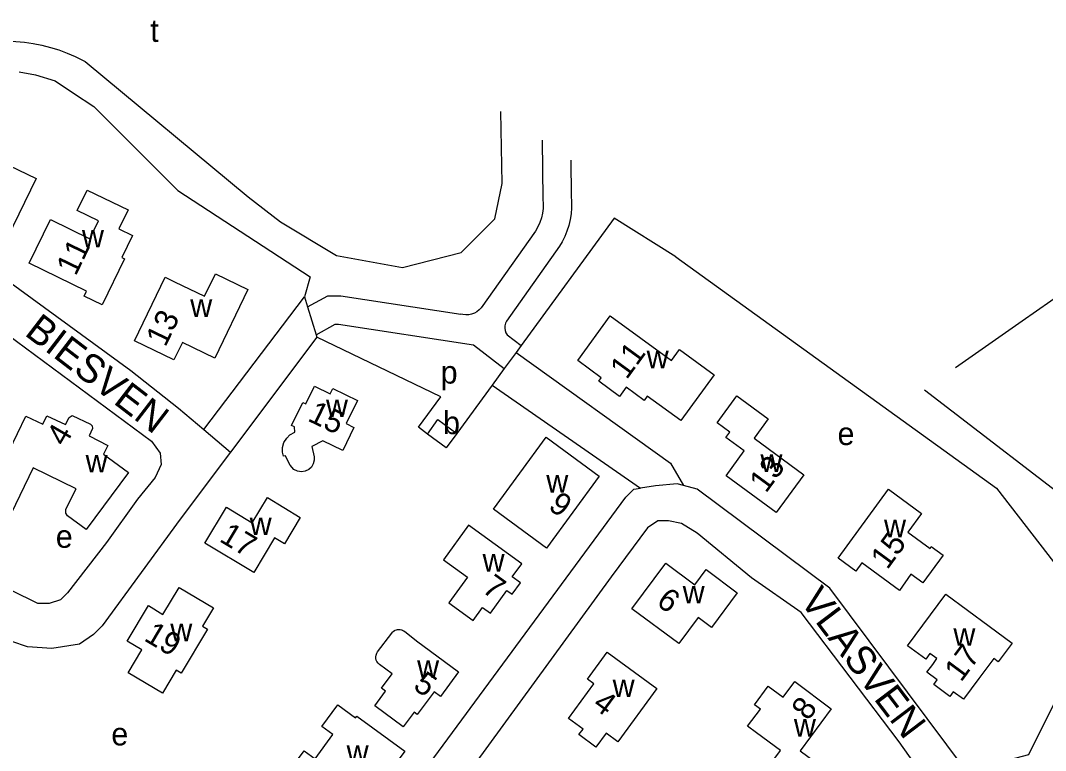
# Model space of a CAD drawing. Extents: x 162667 to 164645, y 379003 to 382150.
# Drawn here: x 163785.6 to 163965.8, y 381498.4 to 381626.7 of the extents above; entities that cross this region are included whole.
import ezdxf

# ---------------------------------------------------------------- set-up
doc = ezdxf.new("R2010")
doc.units = 0
for name, color, linetype in [('BLT_Basislijn', 7, 'Continuous'), ('BLT_Bebouwing', 7, 'Continuous'), ('BLT_Centroide', 7, 'Continuous'), ('BLT_Huisnummer', 7, 'Continuous'), ('BLT_Straatnaam', 7, 'Continuous')]:
    doc.layers.add(name, color=color, linetype=linetype)

msp = doc.modelspace()

# ---------------------------------------------------------------- linework, layer by layer
at = {"layer": 'BLT_Basislijn'}
for p, q in [((163785.42, 381617.69), (163788.3, 381617.15)), ((163788.3, 381617.15), (163791.72, 381616.07)), ((163791.72, 381616.07), (163794.96, 381613.91)), ((163794.96, 381613.91), (163798.56, 381611.57)), ((163798.56, 381611.57), (163813.32, 381596.8)), ((163877.35, 381605.64), (163877.46, 381595.31)), ((163882.35, 381602.16), (163882.43, 381595.86)), ((163813.32, 381596.8), (163836.54, 381581.67)), ((163876.16, 381589.7), (163866.62, 381576.21)), ((163880.38, 381587.02), (163871.08, 381573.87)), ((163836.54, 381581.67), (163835.58, 381578.14)), ((163817.87, 381554.81), (163835.58, 381578.14)), ((163835.58, 381578.14), (163836.11, 381576.38)), ((163836.11, 381576.38), (163837.59, 381571.49)), ((163961.63, 381573.91), (163961.72, 381573.86)), ((163837.59, 381571.49), (163837.73, 381571.04)), ((163871.2, 381571.44), (163873.62, 381569.57)), ((163837.73, 381571.04), (163822.54, 381550.84)), ((163873.62, 381569.57), (163872.75, 381568.38)), ((163872.75, 381568.38), (163870.67, 381565.54)), ((163870.67, 381565.54), (163868.55, 381562.65)), ((163868.55, 381562.65), (163894.62, 381544.54)), ((163817.87, 381554.81), (163822.54, 381550.84))]:
    msp.add_line(p, q, dxfattribs=at)
for points in [[(163771.22, 381620.77), (163772.66, 381621.33), (163774.13, 381621.81), (163775.62, 381622.22), (163777.13, 381622.55), (163778.66, 381622.81), (163780.19, 381622.98), (163781.74, 381623.07), (163783.28, 381623.09), (163784.83, 381623.02), (163786.36, 381622.88), (163787.89, 381622.65), (163789.41, 381622.35), (163790.91, 381621.97), (163792.38, 381621.51), (163793.83, 381620.97), (163795.25, 381620.36), (163796.64, 381619.68), (163797.03, 381619.47)], [(163797.03, 381619.47), (163825.68, 381595.72), (163831.36, 381591.33), (163841.17, 381585.39), (163852.78, 381583.32), (163863.11, 381585.91), (163869.04, 381591.84), (163870.33, 381598.04), (163870.08, 381610.7)], [(164012.05, 381608.99), (163961.72, 381573.86)], [(163877.46, 381595.31), (163877.51, 381594.48), (163877.49, 381593.65), (163877.38, 381592.82), (163877.19, 381592.01), (163876.93, 381591.22), (163876.59, 381590.46), (163876.16, 381589.7)], [(163882.43, 381595.86), (163882.51, 381594.82), (163882.5, 381593.78), (163882.42, 381592.74), (163882.25, 381591.7), (163882.01, 381590.68), (163881.69, 381589.69), (163881.3, 381588.72), (163880.83, 381587.79), (163880.38, 381587.02)], [(163900.81, 381585.17), (163889.99, 381591.98), (163873.62, 381569.57)], [(163900.81, 381585.17), (163957.18, 381544.51), (163974.81, 381521.76)], [(163759.24, 381577.31), (163760.66, 381577.98), (163778.65, 381582.25), (163781.09, 381581.79), (163783.38, 381581.03), (163805.02, 381565.17), (163813.4, 381558.61), (163817.87, 381554.81)], [(163836.11, 381576.38), (163839.69, 381578.33), (163841.94, 381578.33), (163863.05, 381575.11)], [(163866.62, 381576.21), (163866.27, 381575.84), (163865.86, 381575.52), (163865.42, 381575.27), (163864.93, 381575.09), (163864.43, 381574.99), (163863.92, 381574.96), (163863.41, 381575.02), (163863.05, 381575.11)], [(163780.17, 381573.86), (163808.68, 381552.81), (163810.2, 381550.68), (163810.35, 381548.69), (163809.29, 381546.41), (163806.24, 381542.59), (163800.75, 381534.97), (163793.89, 381526.12), (163792.67, 381524.9), (163790.69, 381524.29), (163788.71, 381524.29), (163756.7, 381540), (163755.33, 381541.22), (163754.57, 381543.51), (163755.02, 381547.78), (163759.29, 381567.3), (163760.51, 381569.13), (163762.19, 381570.5), (163778.04, 381574.62), (163780.17, 381573.86)], [(163837.59, 381571.49), (163840.97, 381573.33), (163841.56, 381573.33), (163865.25, 381569.72), (163870.67, 381565.54)], [(163871.08, 381573.87), (163870.9, 381573.49), (163870.8, 381573.07), (163870.78, 381572.65), (163870.84, 381572.23), (163870.97, 381571.83), (163871.2, 381571.44)], [(163961.72, 381573.86), (163949.95, 381565.64)], [(163857.16, 381554.04), (163855.62, 381555.27), (163859.51, 381560.58), (163837.73, 381571.04)], [(163872.75, 381568.38), (163899.9, 381548.92), (163902.16, 381544.97)], [(163868.55, 381562.65), (163862.31, 381554.12)], [(163944.52, 381561.8), (163974.11, 381539.07), (163979.67, 381542.78)], [(163822.54, 381550.84), (163813.71, 381539.08), (163799.99, 381520.32), (163798.46, 381518.8), (163796.02, 381517.12), (163791.15, 381516.36), (163786.88, 381516.66), (163784.14, 381517.58), (163765.54, 381526.73), (163763.56, 381526.12), (163762.49, 381524.75), (163747.85, 381494.11)], [(163849.33, 381433.93), (163866.75, 381458.02), (163868.89, 381460.76), (163869.65, 381462.59), (163869.34, 381465.03), (163868.27, 381466.56), (163854.56, 381476.78), (163852.88, 381479.22), (163851.81, 381482.27), (163851.66, 381485.93), (163852.73, 381489.59), (163892.05, 381542.97), (163893.43, 381544.35), (163894.62, 381544.54)], [(163902.16, 381544.97), (163901.05, 381545.26), (163897.24, 381544.96), (163894.62, 381544.54)], [(163951.94, 381494.82), (163927.87, 381526.96), (163904.55, 381544.35), (163902.16, 381544.97)], [(163914.15, 381528.79), (163904.55, 381536.64), (163901.81, 381538.32), (163899.52, 381538.78), (163897.69, 381538.78), (163895.86, 381537.56), (163889.46, 381528.94), (163859.89, 381488.37), (163858.37, 381485.32), (163858.52, 381482.73), (163859.89, 381480.44), (163908.97, 381444.6), (163911.41, 381443.38), (163913.09, 381443.22), (163915.22, 381443.83), (163917.2, 381445.97), (163947.08, 381486.84), (163947.38, 381488.83), (163946.77, 381490.51), (163940.07, 381499.96), (163922.84, 381522.69), (163914.15, 381528.79)], [(163974.81, 381521.76), (163962.78, 381497.67), (163951.94, 381494.82)]]:
    msp.add_lwpolyline(points, dxfattribs=at)
at = {"layer": 'BLT_Bebouwing'}
msp.add_line((163948.27, 381525.9), (163955.88, 381520.28), dxfattribs=at)
for points in [[(163783.65, 381601.24), (163788.39, 381598.95), (163783.32, 381588.46), (163780.25, 381589.94), (163779.77, 381588.95), (163769.21, 381594.02), (163773.23, 381602.29), (163782.11, 381598.05), (163783.65, 381601.24)], [(163797.37, 381596.91), (163804.56, 381593.43), (163802.94, 381590.1), (163805.36, 381588.92), (163803.48, 381585.03), (163803.93, 381584.82), (163799.99, 381576.72), (163796.82, 381578.26), (163797.26, 381579.15), (163787.19, 381584.04), (163790.91, 381591.7), (163797.84, 381588.33), (163799.37, 381591.47), (163795.61, 381593.29), (163797.37, 381596.91)], [(163819.93, 381582.2), (163825.62, 381579.45), (163819.79, 381567.37), (163814.1, 381570.11), (163812.62, 381567.05), (163805.66, 381570.41), (163811.06, 381581.6), (163812.73, 381580.79), (163818, 381578.24), (163819.93, 381582.2)], [(163889.3, 381574.78), (163900.05, 381566.93), (163901.46, 381568.87), (163907.55, 381564.43), (163901.7, 381556.41), (163895.81, 381560.71), (163895.26, 381559.95), (163892.11, 381562.25), (163890.93, 381560.63), (163887.27, 381563.3), (163887.73, 381563.93), (163883.59, 381566.95), (163889.3, 381574.78)], [(163837.32, 381562.46), (163840.09, 381561.12), (163840.53, 381562.02), (163844.87, 381559.91), (163842.91, 381555.86), (163844.26, 381555.21), (163842.3, 381551.15), (163838.79, 381552.85), (163836.88, 381551.85), (163837.29, 381550.03), (163837.29, 381549.42), (163837.11, 381548.81), (163836.78, 381548.24), (163836.31, 381547.81), (163835.68, 381547.52), (163835.03, 381547.42), (163834.35, 381547.51), (163833.71, 381547.8), (163833.07, 381548.58), (163832.57, 381549.43), (163832.25, 381550.18), (163831.86, 381550.15), (163831.71, 381550.84), (163831.72, 381551.69), (163831.96, 381552.54), (163832.44, 381553.31), (163833.01, 381553.89), (163833.86, 381554.34), (163833.78, 381555.28), (163833.29, 381555.51), (163835.25, 381559.57), (163835.8, 381559.32), (163837.32, 381562.46)], [(163911.57, 381560.74), (163917.07, 381556.7), (163914.58, 381553.3), (163923.31, 381546.88), (163918.45, 381540.26), (163909.65, 381546.72), (163912.84, 381551.06), (163909.62, 381553.43), (163910.31, 381554.36), (163908.08, 381556), (163911.57, 381560.74)], [(163786.59, 381557.17), (163789.55, 381555.75), (163790.28, 381557.26), (163793.57, 381555.7), (163794.2, 381556.93), (163794.73, 381557.31), (163797.93, 381555.79), (163798.24, 381555.48), (163798.31, 381555.02), (163797.74, 381553.71), (163800.97, 381552.04), (163800.25, 381550.51), (163804.65, 381547.28), (163797.18, 381537.24), (163793.89, 381539.69), (163793.59, 381540.15), (163793.59, 381540.84), (163795.42, 381544.42), (163787.87, 381548.09), (163783.18, 381538.39), (163777.73, 381541.03), (163782.79, 381551.49), (163783.64, 381551.08), (163786.59, 381557.17)], [(163857.16, 381554.04), (163859, 381556.58), (163862.31, 381554.12)], [(163862.31, 381554.12), (163860.47, 381551.6), (163857.16, 381554.04)], [(163878.01, 381553.5), (163887.38, 381546.65), (163878.12, 381534), (163868.76, 381540.85), (163878.01, 381553.5)], [(163938.21, 381544.34), (163944.01, 381540.09), (163941.6, 381536.8), (163945.51, 381533.94), (163945.7, 381534.29), (163947.79, 381532.75), (163944.21, 381527.88), (163942.12, 381529.41), (163940.11, 381526.57), (163933.53, 381531.4), (163932.47, 381529.95), (163929.35, 381532.23), (163938.21, 381544.34)], [(163829.04, 381542.87), (163834.82, 381539.4), (163832.04, 381534.76), (163830.3, 381535.81), (163826.63, 381529.7), (163818.05, 381534.86), (163821.84, 381541.18), (163826.39, 381538.45), (163829.04, 381542.87)], [(163873.74, 381531.23), (163864.39, 381538.02), (163859.97, 381531.92), (163864.2, 381528.86), (163860.93, 381524.35), (163865.18, 381521.26), (163866.84, 381523.55), (163868.23, 381522.55), (163871.15, 381526.57), (163872.07, 381525.9), (163873.51, 381527.88), (163872.07, 381528.92), (163873.74, 381531.23)], [(163899.06, 381531.36), (163904.18, 381527.56), (163906.14, 381530.21), (163911.61, 381526.15), (163907.09, 381520.05), (163904.73, 381521.8), (163901.34, 381517.24), (163893.11, 381523.33), (163899.06, 381531.36)], [(163813.51, 381527.08), (163819.55, 381523.48), (163817.63, 381520.26), (163818.49, 381519.75), (163813.88, 381512.02), (163813.02, 381512.53), (163810.6, 381508.48), (163804.55, 381512.08), (163806.97, 381516.13), (163804.4, 381517.66), (163808.12, 381523.89), (163810.69, 381522.35), (163813.51, 381527.08)], [(163954.08, 381511.09), (163951.38, 381507.43), (163949.58, 381508.75), (163948.99, 381507.95), (163946.18, 381510.03), (163946.78, 381510.83), (163944.95, 381512.18), (163945.98, 381513.57), (163946.7, 381514.59), (163945.49, 381515.46), (163944.77, 381514.46), (163941.56, 381516.84), (163948.27, 381525.9)], [(163855.24, 381517.71), (163862.64, 381512.25), (163859.45, 381507.94), (163858.35, 381508.76), (163855.38, 381504.76), (163854.81, 381505.19), (163852.91, 381502.62), (163847.92, 381506.3), (163849.82, 381508.87), (163849.1, 381509.4), (163850.96, 381511.89), (163848.74, 381513.54), (163848.5, 381513.75), (163848.29, 381514.05), (163848.17, 381514.33), (163848.12, 381514.59), (163848.1, 381514.88), (163848.14, 381515.18), (163848.26, 381515.51), (163848.42, 381515.77), (163850.89, 381519.07), (163851.02, 381519.22), (163851.16, 381519.35), (163851.37, 381519.49), (163851.51, 381519.56), (163851.71, 381519.64), (163851.93, 381519.68), (163852.14, 381519.7), (163852.38, 381519.68), (163852.59, 381519.64), (163852.78, 381519.58), (163852.97, 381519.48), (163853.11, 381519.39), (163855.24, 381517.71)], [(163955.88, 381520.28), (163959.92, 381517.29), (163957.5, 381514.02), (163956.69, 381514.61), (163954.08, 381511.09)], [(163888.76, 381515.69), (163897.47, 381509.31), (163890.62, 381499.96), (163888.56, 381501.47), (163886.78, 381499.04), (163883.8, 381501.22), (163884.52, 381502.21), (163881.96, 381504.08), (163886.41, 381510.16), (163885.31, 381510.97), (163888.76, 381515.69)], [(163921.73, 381510.53), (163928.14, 381505.77), (163922.67, 381498.4), (163925.6, 381496.23), (163921.87, 381491.2), (163916.7, 381495.03), (163919.21, 381498.41), (163915.03, 381501.52), (163913.45, 381502.69), (163915.68, 381505.7), (163914.65, 381506.47), (163917.08, 381509.75), (163919.7, 381507.8), (163921.73, 381510.53)], [(163844.77, 381504.48), (163853.17, 381498.33), (163849.67, 381493.55), (163848.82, 381494.17), (163843.46, 381486.84), (163835.9, 381492.37), (163832.77, 381494.66), (163835.49, 381498.39), (163837.44, 381496.96), (163840.56, 381501.22), (163838.61, 381502.64), (163841.41, 381506.46), (163844.54, 381504.16), (163844.77, 381504.48)]]:
    msp.add_lwpolyline(points, dxfattribs=at)

# ---------------------------------------------------------------- texts
at = {"layer": 'BLT_Centroide'}
for s, p in [('t', (163808.45, 381622.93)), ('w', (163796.45, 381586.81)), ('w', (163815.48, 381574.62)), ('w', (163895.7, 381565.59)), ('p', (163859.49, 381562.9)), ('w', (163839.34, 381557.03)), ('b', (163859.92, 381554.02)), ('e', (163929.25, 381552.1)), ('w', (163797.09, 381547.28)), ('w', (163915.7, 381547.38)), ('w', (163878.06, 381543.75)), ('w', (163825.93, 381536.28)), ('w', (163937.42, 381535.89)), ('e', (163791.85, 381534.05)), ('w', (163866.86, 381529.88)), ('w', (163902.03, 381524.28)), ('w', (163811.98, 381517.64)), ('w', (163949.61, 381516.83)), ('w', (163855.36, 381511.2)), ('w', (163889.72, 381507.81)), ('w', (163921.58, 381500.88)), ('e', (163801.61, 381499.33)), ('w', (163842.97, 381496.25))]:
    msp.add_text(s, height=4, dxfattribs=at).set_placement(p)
at = {"layer": 'BLT_Huisnummer'}
for s, rotation, p in [('11', 64.1302, (163795.35, 381581.67)), ('13', 64.2433, (163811.11, 381569.18)), ('11', 53.8728, (163892.18, 381563.47)), ('15', 334.1864, (163835.93, 381556.45)), ('4', 59.7663, (163793.43, 381551.68)), ('13', 53.7016, (163916.66, 381543.51)), ('9', 323.8067, (163878.22, 381540.97)), ('17', 329.0205, (163820.42, 381535.28)), ('15', 53.7829, (163937.99, 381530.07)), ('7', 324.048, (163866.57, 381526.44)), ('6', 323.449, (163897.21, 381524.15)), ('19', 329.2289, (163807.17, 381517.86)), ('17', 53.5026, (163950.96, 381510.32)), ('5', 323.5351, (163854.47, 381509.41)), ('4', 323.7869, (163886.01, 381506.09)), ('8', 53.3987, (163924.07, 381503.52))]:
    msp.add_text(s, height=4, rotation=rotation, dxfattribs=at).set_placement(p)
at = {"layer": 'BLT_Straatnaam'}
for s, rotation, p in [('BIESVEN', 322.4605, (163786.18, 381571.53)), ('VLASVEN', 307.1584, (163922.48, 381524.7))]:
    msp.add_text(s, height=5, rotation=rotation, dxfattribs=at).set_placement(p)

doc.saveas('drawing.dxf')
